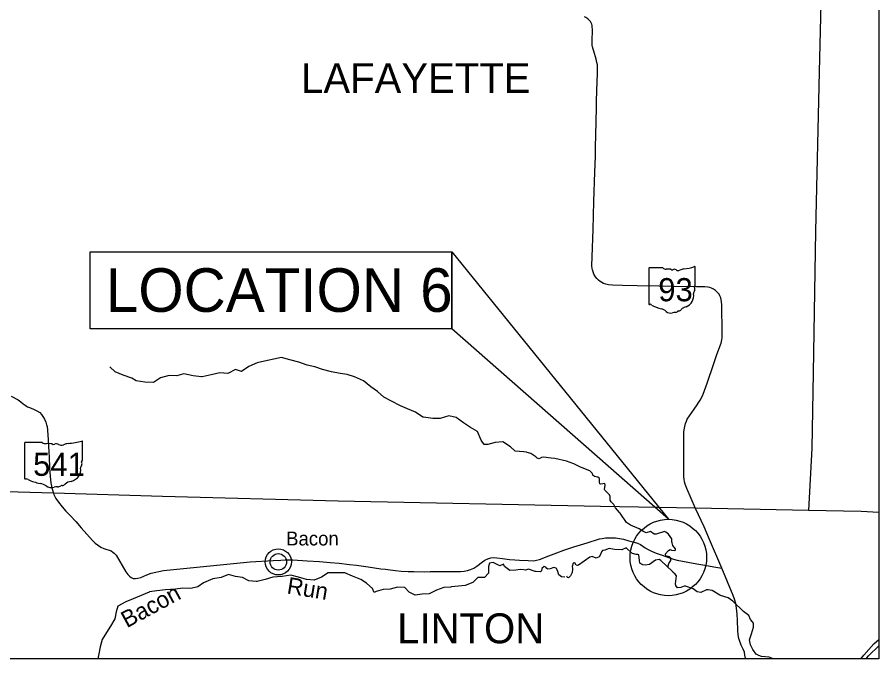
# Model space of a CAD drawing. Extents: x -6.3 to 34, y 0 to 22.
# Drawn here: x 8.831 to 12.189, y 9.388 to 11.89 of the extents above; entities that cross this region are included whole.
import ezdxf

# ---------------------------------------------------------------- set-up
doc = ezdxf.new("R2010")
doc.units = 0
for name, color, linetype in [('BR_P_Gen_Text', 7, 'Continuous'), ('Default', 7, 'Continuous'), ('GM_X_Major_River', 7, 'Continuous'), ('GM_X_Minor_River', 7, 'Continuous'), ('GM_X_Minor_River_Text', 7, 'Continuous'), ('GM_X_State_Route', 7, 'Continuous'), ('GM_X_State_Shield', 7, 'Continuous'), ('GM_X_Township', 7, 'Continuous'), ('GM_X_Township_Text', 7, 'Continuous'), ('GM_X_Unincorporated', 7, 'Continuous'), ('GM_X_Unincorporated_Location', 7, 'Continuous'), ('GM_X_Unincorporated_Text', 7, 'Continuous'), ('SH_Text', 7, 'Continuous')]:
    doc.layers.add(name, color=color, linetype=linetype)

msp = doc.modelspace()

# ---------------------------------------------------------------- linework, layer by layer
at = {"layer": 'BR_P_Gen_Text'}
for points in [[(9.1155, 10.9748), (10.5242, 10.9748), (10.5242, 10.6746), (9.1155, 10.6746)], [(10.5242, 10.6746), (10.5242, 10.9748), (11.3687, 9.9324)]]:
    msp.add_lwpolyline(points, close=True, dxfattribs=at)
at = {"layer": 'Default'}
msp.add_circle((11.3687, 9.7834), 0.149, dxfattribs=at)
at = {"layer": 'GM_X_Major_River'}
for points in [[(12.1192, 9.3884), (12.1301, 9.4028), (12.1695, 9.4464), (12.189, 9.4639)], [(12.1399, 9.3884), (12.1495, 9.3998), (12.189, 9.4394)]]:
    msp.add_lwpolyline(points, dxfattribs=at)
at = {"layer": 'GM_X_Minor_River'}
for points in [[(10.772, 10.1977), (10.7536, 10.215), (10.723, 10.2344), (10.6938, 10.2318), (10.6651, 10.2239), (10.6506, 10.2242), (10.6397, 10.2415), (10.6251, 10.2745), (10.5979, 10.2905), (10.5697, 10.3084), (10.5422, 10.3289), (10.5134, 10.3353), (10.4796, 10.3261), (10.4509, 10.3258), (10.4138, 10.3309), (10.4123, 10.3312), (10.3827, 10.3501), (10.3517, 10.3638), (10.325, 10.3744), (10.2895, 10.3932), (10.2602, 10.4088), (10.2345, 10.4305), (10.2086, 10.4484), (10.1806, 10.4725), (10.1451, 10.488), (10.1169, 10.4965), (10.0892, 10.5011), (10.0563, 10.5073), (10.0211, 10.5168), (9.9942, 10.5259), (9.9911, 10.5266), (9.961, 10.5341), (9.9287, 10.5455), (9.8929, 10.5542), (9.8603, 10.563), (9.8306, 10.5572), (9.8057, 10.5512), (9.7664, 10.542), (9.7339, 10.5281), (9.7052, 10.5091), (9.6809, 10.5169), (9.6511, 10.5004), (9.6198, 10.504), (9.5865, 10.4959), (9.551, 10.488), (9.5495, 10.4885), (9.5164, 10.4913), (9.4801, 10.4995), (9.453, 10.492), (9.4232, 10.4937), (9.3888, 10.4846), (9.3622, 10.4663), (9.3283, 10.467), (9.2941, 10.4729), (9.2768, 10.4828), (9.2442, 10.4939), (9.212, 10.5076), (9.1921, 10.527)], [(11.3673, 9.7453), (11.3708, 9.7596), (11.3784, 9.772), (11.379, 9.7803), (11.3738, 9.7855), (11.3681, 9.7874), (11.3591, 9.789), (11.3576, 9.7973), (11.3693, 9.8113), (11.3753, 9.8146), (11.3815, 9.8125), (11.3936, 9.8106), (11.3962, 9.8122), (11.397, 9.8174), (11.386, 9.8302), (11.3832, 9.8411), (11.3827, 9.8439), (11.3828, 9.8564), (11.3697, 9.8744), (11.3583, 9.8828), (11.3531, 9.8844), (11.3207, 9.875), (11.314, 9.875), (11.2995, 9.8847), (11.2824, 9.8801), (11.2713, 9.8851), (11.2548, 9.8949), (11.221, 9.9091), (11.2052, 9.9198), (11.1809, 9.9564), (11.1785, 9.9592), (11.1631, 9.9765), (11.1559, 9.9906), (11.1454, 10.001), (11.1415, 10.0068), (11.1414, 10.0218), (11.1388, 10.0278), (11.121, 10.0456), (11.1198, 10.0485), (11.1224, 10.0659), (11.1207, 10.0721), (11.1062, 10.0696), (11.1023, 10.0704), (11.1, 10.0756), (11.1001, 10.092), (11.0941, 10.0969), (11.0807, 10.0988), (11.075, 10.1041), (11.073, 10.1103), (11.072, 10.1129), (11.0629, 10.1208), (11.026, 10.1356), (10.9997, 10.1482), (10.9712, 10.1587), (10.926, 10.1694), (10.9123, 10.1705), (10.8825, 10.1751), (10.8737, 10.1731), (10.8654, 10.1682), (10.8574, 10.1709), (10.8528, 10.1766), (10.8329, 10.1892), (10.8189, 10.1932), (10.8158, 10.194), (10.8055, 10.1959), (10.772, 10.1977)], [(11.7769, 9.3884), (11.7685, 9.3924), (11.7615, 9.3951), (11.7315, 9.3971), (11.7214, 9.4013), (11.7189, 9.4028), (11.7116, 9.4068), (11.6975, 9.425), (11.6893, 9.4425), (11.6848, 9.462), (11.6932, 9.4856), (11.7001, 9.5121), (11.7001, 9.5271), (11.6973, 9.5329), (11.6893, 9.541), (11.6819, 9.5566), (11.6621, 9.5723), (11.6196, 9.6134), (11.6018, 9.6257), (11.5726, 9.6357), (11.5695, 9.637), (11.5393, 9.6541), (11.5235, 9.6576), (11.5178, 9.6571), (11.4952, 9.6471), (11.481, 9.65), (11.4658, 9.6618), (11.4361, 9.6713), (11.4301, 9.6716), (11.4179, 9.6668), (11.4047, 9.6656), (11.3978, 9.6737), (11.3968, 9.6807), (11.4003, 9.7116), (11.3957, 9.7186), (11.3867, 9.7262), (11.3846, 9.7288), (11.3396, 9.7717), (11.3326, 9.7759), (11.3183, 9.7731), (11.2952, 9.7566), (11.2781, 9.7536), (11.269, 9.7544), (11.2579, 9.7618), (11.2557, 9.7722), (11.2535, 9.7935), (11.2501, 9.7956), (11.2436, 9.7946), (11.2286, 9.7989), (11.226, 9.8004), (11.2042, 9.8208), (11.1868, 9.8139), (11.1583, 9.8146), (11.1386, 9.8189), (11.1212, 9.812), (11.1124, 9.8112), (11.108, 9.8061), (11.1048, 9.7947), (11.0993, 9.7859), (11.0877, 9.7802), (11.0722, 9.7868), (11.0631, 9.7853), (11.0181, 9.7538), (11.015, 9.752), (11.0088, 9.7536), (11.0042, 9.7622), (10.9972, 9.7607), (10.994, 9.7488), (10.9955, 9.7407), (10.9952, 9.7379), (10.9939, 9.7244), (10.9873, 9.7122), (10.979, 9.7047), (10.9759, 9.7052), (10.9731, 9.7107)], [(10.7744, 9.734), (10.7515, 9.7327), (10.7307, 9.7485), (10.7268, 9.7573), (10.7121, 9.7513), (10.6854, 9.7642), (10.6714, 9.7608), (10.6678, 9.7489), (10.6676, 9.7218), (10.6522, 9.7054), (10.6255, 9.7054), (10.6064, 9.6856), (10.5769, 9.6741), (10.5506, 9.6717), (10.5226, 9.6688), (10.5211, 9.668), (10.4936, 9.6669), (10.4647, 9.6565), (10.4368, 9.6416), (10.4086, 9.641), (10.3817, 9.6368), (10.3591, 9.6477), (10.3418, 9.6668), (10.3136, 9.6673), (10.2848, 9.6602), (10.2574, 9.6589), (10.2295, 9.6508), (10.2215, 9.6471), (10.2155, 9.6627), (10.1932, 9.6826), (10.1916, 9.6834), (10.1696, 9.6979), (10.1372, 9.7103), (10.1077, 9.7235), (10.0746, 9.7239), (10.0433, 9.7231), (10.0167, 9.7069), (9.988, 9.6949), (9.9577, 9.6977), (9.9269, 9.7062), (9.8971, 9.7145), (9.8635, 9.7089), (9.8268, 9.7065), (9.7965, 9.6979), (9.7655, 9.6898), (9.7626, 9.6892), (9.7339, 9.6918), (9.7088, 9.7052), (9.6816, 9.7099), (9.6539, 9.7171), (9.6257, 9.7053), (9.5929, 9.7008), (9.5572, 9.6849), (9.5342, 9.6688), (9.5068, 9.662), (9.4768, 9.6632), (9.4473, 9.6593), (9.409, 9.6568), (9.3754, 9.6534), (9.3459, 9.65), (9.3444, 9.6484), (9.3141, 9.6351), (9.2831, 9.6223), (9.2534, 9.6103), (9.2231, 9.5942), (9.2162, 9.5721), (9.2116, 9.544), (9.1946, 9.5162), (9.1781, 9.4907), (9.1619, 9.4637), (9.1534, 9.4354), (9.1486, 9.4081), (9.1443, 9.3884)], [(10.9647, 9.7068), (10.9518, 9.708), (10.9415, 9.7164), (10.9364, 9.7333), (10.9311, 9.7416), (10.9223, 9.744), (10.908, 9.7386), (10.8984, 9.7384), (10.8953, 9.7403), (10.8907, 9.746), (10.8847, 9.7489), (10.8754, 9.7404), (10.8743, 9.7311), (10.8701, 9.7274), (10.8538, 9.7288), (10.8502, 9.7291), (10.8238, 9.7376), (10.8119, 9.7335), (10.8054, 9.7351), (10.7909, 9.737), (10.7744, 9.734)]]:
    msp.add_lwpolyline(points, dxfattribs=at)
at = {"layer": 'GM_X_State_Route'}
msp.add_line((11.6216, 9.6357), (11.5769, 9.7423), dxfattribs=at)
for points in [[(11.5769, 9.7423), (11.5297, 9.8531), (11.5081, 9.9035), (11.4752, 9.9751), (11.4574, 10.0134), (11.4407, 10.0531), (11.4372, 10.0631), (11.4348, 10.0698), (11.4321, 10.0785), (11.4301, 10.0887), (11.4291, 10.0977), (11.4285, 10.1113), (11.4287, 10.1676), (11.4288, 10.2538), (11.4294, 10.2724), (11.4307, 10.2818), (11.4332, 10.2949), (11.436, 10.3056), (11.4393, 10.3148), (11.4424, 10.323), (11.4697, 10.3618), (11.4814, 10.379), (11.4882, 10.3895), (11.4924, 10.3968), (11.4991, 10.4088), (11.5043, 10.4201), (11.5102, 10.4351), (11.5201, 10.4629), (11.546, 10.54), (11.557, 10.5715), (11.5697, 10.6065), (11.574, 10.6193), (11.5774, 10.632), (11.5784, 10.6396), (11.5789, 10.653), (11.5782, 10.6854), (11.5771, 10.7427), (11.5768, 10.7684), (11.5761, 10.78), (11.5748, 10.7889), (11.5728, 10.7959), (11.57, 10.8033), (11.5662, 10.8101), (11.562, 10.8161), (11.5581, 10.8197), (11.5529, 10.8245), (11.5443, 10.8301), (11.5371, 10.8337), (11.5303, 10.8359), (11.5224, 10.8375), (11.5107, 10.8386), (11.4782, 10.8393), (11.3914, 10.84), (11.332, 10.8409), (11.2476, 10.8431), (11.1897, 10.8444), (11.151, 10.8451), (11.1351, 10.8465), (11.1252, 10.8489), (11.1163, 10.852), (11.1096, 10.8553), (11.1033, 10.8591), (11.096, 10.8648), (11.09, 10.8708), (11.0842, 10.8783), (11.0786, 10.8888), (11.0753, 10.8974), (11.0728, 10.9056), (11.0717, 10.9099), (11.0705, 10.921), (11.0714, 10.9561), (11.0752, 11.0624), (11.0787, 11.1723), (11.0821, 11.2857), (11.0844, 11.3477), (11.0845, 11.3637), (11.0854, 11.3833), (11.0879, 11.4808), (11.0888, 11.5394), (11.0893, 11.5627), (11.0905, 11.6027), (11.0923, 11.6716), (11.0927, 11.696), (11.0922, 11.7049), (11.0905, 11.7142), (11.0874, 11.7266), (11.0779, 11.7576), (11.0752, 11.7656), (11.0728, 11.775), (11.072, 11.7816), (11.0715, 11.7884), (11.0715, 11.7964), (11.0728, 11.841), (11.0724, 11.8538), (11.0717, 11.8583), (11.0705, 11.8632), (11.0679, 11.8688), (11.0647, 11.8735), (11.0601, 11.8791), (11.0544, 11.8844), (11.0476, 11.8889), (11.0421, 11.8914)], [(8.8074, 10.4129), (8.8342, 10.3983), (8.845, 10.3909), (8.854, 10.3828), (8.8619, 10.377)], [(8.8619, 10.377), (8.8664, 10.374), (8.8703, 10.3714), (8.8824, 10.3667), (8.8968, 10.3612), (8.9077, 10.3559), (8.9185, 10.3483), (8.9247, 10.3416), (8.931, 10.3327), (8.9366, 10.3223), (8.9417, 10.3114), (8.9453, 10.3013), (8.9473, 10.2938), (8.9493, 10.2806), (8.9514, 10.2418), (8.9543, 10.1941), (8.955, 10.1755), (8.9566, 10.1335), (8.9591, 10.0987), (8.9623, 10.0747), (8.9657, 10.0554), (8.9718, 10.0338), (8.9734, 10.0296), (8.9818, 10.0135), (8.9916, 9.9987), (9.0053, 9.9806), (9.0198, 9.9642), (9.0382, 9.946), (9.0596, 9.9235), (9.0805, 9.8997), (9.1022, 9.8746), (9.124, 9.8501), (9.1345, 9.8398), (9.147, 9.8299), (9.1565, 9.8235), (9.1682, 9.8185), (9.1965, 9.809), (9.2038, 9.8048), (9.2092, 9.8004), (9.2157, 9.7924), (9.2541, 9.7278), (9.2616, 9.7168), (9.2678, 9.7101), (9.2742, 9.7048), (9.2828, 9.7021), (9.2923, 9.7015), (9.3014, 9.7026), (9.3128, 9.706), (9.3356, 9.7152), (9.353, 9.7219), (9.4011, 9.7327), (9.7383, 9.7661), (9.8284, 9.7711), (9.8579, 9.7732), (9.8757, 9.774), (9.9052, 9.7738), (9.9608, 9.7705), (10.0083, 9.7674), (10.0507, 9.7643), (10.0856, 9.7612), (10.1265, 9.7562), (10.1533, 9.7531), (10.1988, 9.7467), (10.2476, 9.7398), (10.2657, 9.7374), (10.2845, 9.7353), (10.3048, 9.7331), (10.3277, 9.7306), (10.3542, 9.7289), (10.3769, 9.7283), (10.4186, 9.7281), (10.4399, 9.7283), (10.4686, 9.7287), (10.53, 9.7285), (10.5581, 9.7287), (10.5727, 9.7298), (10.586, 9.7325), (10.5972, 9.736), (10.6102, 9.7422), (10.6226, 9.7501), (10.6437, 9.7669), (10.6533, 9.7729), (10.6653, 9.7782), (10.6762, 9.7816), (10.6878, 9.7828), (10.6999, 9.7823), (10.7221, 9.7794), (10.7494, 9.7757), (10.7699, 9.7738), (10.7885, 9.7729), (10.8229, 9.7713), (10.8441, 9.7707), (10.8553, 9.7724), (10.8664, 9.7758), (10.9027, 9.7899), (10.934, 9.802), (10.9618, 9.8118), (11, 9.8245), (11.0522, 9.8405), (11.1007, 9.8556), (11.1108, 9.8581), (11.1239, 9.86), (11.1473, 9.8607), (11.163, 9.8597), (11.1788, 9.8571), (11.1936, 9.8543), (11.2152, 9.849), (11.2355, 9.8437), (11.2482, 9.8391), (11.2596, 9.8337), (11.278, 9.8216), (11.2896, 9.8147), (11.3027, 9.808), (11.3214, 9.8009), (11.3453, 9.792), (11.3687, 9.7834), (11.3891, 9.7771), (11.4036, 9.7734), (11.4233, 9.7691), (11.4445, 9.7655), (11.4799, 9.7593), (11.4874, 9.7579), (11.5108, 9.7537), (11.546, 9.7474), (11.5769, 9.7423)], [(11.6499, 9.4488), (11.6468, 9.4562), (11.6431, 9.4681), (11.6404, 9.4816), (11.6393, 9.4981), (11.6382, 9.5386), (11.6372, 9.5624), (11.6345, 9.5858), (11.6313, 9.6034), (11.6264, 9.6203), (11.6216, 9.6357)], [(11.669, 9.3884), (11.6689, 9.3909), (11.6675, 9.4023), (11.665, 9.414), (11.66, 9.4262), (11.653, 9.4414), (11.6499, 9.4488)]]:
    msp.add_lwpolyline(points, dxfattribs=at)
at = {"layer": 'GM_X_State_Shield'}
for p, q in [((11.4734, 10.8441), (11.4734, 10.9158)), ((11.2927, 10.9101), (11.2927, 10.7729)), ((11.3474, 10.9124), (11.2945, 10.9124)), ((11.4734, 10.8441), (11.4734, 10.8441)), ((8.8594, 10.2293), (8.8594, 10.0921)), ((8.9278, 10.2316), (8.8616, 10.2316)), ((9.0853, 10.1633), (9.0853, 10.235)), ((9.0853, 10.1633), (9.0853, 10.1633))]:
    msp.add_line(p, q, dxfattribs=at)
for centre, radius, start, end in [((11.409, 11.0994), 0.1916, 275.8445, 288.9065), ((11.4714, 10.9161), 0.00201, 351.8621, 97.738), ((11.2948, 10.9104), 0.00209, 98.1301, 188.1301), ((11.36, 10.9284), 0.0203, 231.6195, 271.1119), ((11.3667, 10.8354), 0.0729, 80.4867, 94.9883), ((11.3833, 10.9111), 0.00586, 219.7921, 297.1024), ((11.3919, 10.8952), 0.0122, 54.4667, 119.1411), ((11.4076, 10.917), 0.0147, 233.8562, 294.8282), ((11.4335, 10.8705), 0.0386, 97.3462, 120.7689), ((11.4806, 10.8141), 0.0136, 136.8065, 186.9296), ((11.4729, 10.8388), 0.00311, 107.944, 210.337), ((11.4531, 10.8298), 0.0187, 340.033, 23.6496), ((11.4712, 10.8438), 0.00215, 289.6038, 7.7341), ((11.4198, 10.8049), 0.0479, 292.3089, 8.9858), ((11.2948, 10.7726), 0.00211, 171.9584, 258.3066), ((11.2951, 10.7867), 0.0161, 267.339, 280.6039), ((11.2984, 10.765), 0.00581, 29.7484, 93.2717), ((11.3718, 10.8882), 0.1384, 240.4129, 257.1985), ((11.3305, 10.7113), 0.0433, 47.1842, 75.836), ((11.4067, 10.7596), 0.0155, 282.8732, 323.2771), ((11.44, 10.7344), 0.0263, 94.4031, 142.5768), ((11.3773, 10.7643), 0.0275, 230.7004, 286.2918), ((11.3932, 10.7169), 0.0226, 85.6951, 111.2099), ((11.3952, 10.7541), 0.0146, 268.777, 315.5493), ((11.4085, 10.7408), 0.00412, 65.7517, 132.6484)]:
    msp.add_arc(centre, radius, start, end, dxfattribs=at)
for centre, major_axis, start_param, end_param in [((8.862, 10.2296), (0.00262, 0), 1.712693, 3.28349), ((8.9435, 10.2475), (0.0254, 0), 4.042523, 4.731795), ((8.952, 10.1546), (0.0911, 0), 1.404758, 1.657858), ((8.9727, 10.2303), (0.00732, 0), 3.836095, 5.185415), ((8.9834, 10.2144), (0.0152, 0), 0.950623, 2.079405), ((9.003, 10.2362), (0.0183, 0), 4.081561, 5.145723), ((9.0354, 10.1897), (0.0482, 0), 1.699011, 2.107814), ((9.0048, 10.4186), (0.2395, 0), 4.814394, 5.042369), ((9.0828, 10.2353), (0.00251, 0), 6.141152, 7.989035), ((9.0943, 10.1333), (0.017, 0), 2.387724, 3.262537), ((9.0847, 10.158), (0.00389, 0), 1.883978, 3.671073), ((9.06, 10.1489), (0.0234, 0), 5.934695, 6.695948), ((9.0826, 10.163), (0.00269, 0), 5.05454, 6.418171), ((9.0183, 10.1241), (0.0599, 0), 5.101752, 6.440018), ((8.862, 10.0918), (0.00264, 0), 3.00124, 4.508301), ((8.8624, 10.1058), (0.0201, 0), 4.665946, 4.897461), ((8.8666, 10.0842), (0.00726, 0), 0.519207, 1.627899), ((8.9583, 10.2074), (0.173, 0), 4.195997, 4.488961), ((9.0435, 10.0536), (0.0328, 0), 1.647645, 2.488434), ((8.9067, 10.0305), (0.0541, 0), 0.823519, 1.323587), ((8.9652, 10.0835), (0.0343, 0), 4.026481, 4.996735), ((8.9851, 10.0361), (0.0282, 0), 1.495662, 1.94098), ((8.9876, 10.0733), (0.0183, 0), 4.691044, 5.507374), ((9.0041, 10.06), (0.00515, 0), 1.147584, 2.315152), ((9.0019, 10.0788), (0.0194, 0), 4.937069, 5.64225)]:
    msp.add_ellipse(centre, major_axis=major_axis, ratio=0.8, start_param=start_param, end_param=end_param, dxfattribs=at)
at = {"layer": 'GM_X_Township'}
for points in [[(12.189, 13.4049), (12.1616, 13.4057), (11.9837, 13.4105), (11.9832, 13.39), (11.9842, 13.205), (11.9845, 13.1562), (11.9852, 13.0258), (11.9853, 13.0174), (11.9723, 12.3546), (11.9703, 12.2549), (11.968, 12.1557), (11.9645, 11.9991), (11.9572, 11.6777), (11.9421, 11.0563), (11.9336, 10.5039), (11.9284, 10.2095), (11.9156, 9.9669)], [(12.189, 9.9587), (12.1204, 9.9622), (11.9156, 9.9669), (11.475, 9.9755), (11.1042, 9.9827), (10.0814, 10.0027), (9.397, 10.0212), (8.9717, 10.0342), (8.7413, 10.0412), (8.7306, 9.6805), (8.7219, 9.3905), (8.7218, 9.3884)]]:
    msp.add_lwpolyline(points, dxfattribs=at)
at = {"layer": 'GM_X_Unincorporated'}
for radius in [0.051, 0.0323]:
    msp.add_circle((9.8484, 9.7663), radius, dxfattribs=at)
at = {"layer": 'GM_X_Unincorporated_Location'}
msp.add_line((9.8484, 9.7663), (9.8484, 9.7663), dxfattribs=at)
at = {"layer": 'SH_Text'}
msp.add_lwpolyline([(1.8145, 20.7482), (12.189, 20.7482), (12.189, 9.3884), (1.8145, 9.3884)], close=True, dxfattribs=at)

# ---------------------------------------------------------------- texts
at = {"layer": 'BR_P_Gen_Text'}
msp.add_text('LOCATION 6', height=0.17, dxfattribs=at).set_placement((9.1762, 10.7414))
at = {"layer": 'GM_X_Minor_River_Text'}
for s, height, rotation, p in [('Run', 0.0649, 350.5841, (9.8791, 9.6436)), ('Bacon', 0.06488, 28.5516, (9.2582, 9.5072))]:
    msp.add_text(s, height=height, rotation=rotation, dxfattribs=at).set_placement(p)
at = {"layer": 'GM_X_State_Shield'}
for s, p in [('93', (11.3295, 10.7826)), ('541', (8.8927, 10.1018))]:
    msp.add_text(s, height=0.09035, dxfattribs=at).set_placement(p)
at = {"layer": 'GM_X_Township_Text'}
for s, p in [('LAFAYETTE', (9.9373, 11.5944)), ('LINTON', (10.3118, 9.4487))]:
    msp.add_text(s, height=0.11682, rotation=0, dxfattribs=at).set_placement(p)
at = {"layer": 'GM_X_Unincorporated_Text'}
msp.add_text('Bacon', height=0.05413, rotation=0, dxfattribs=at).set_placement((9.8788, 9.8303))

doc.saveas('drawing.dxf')
